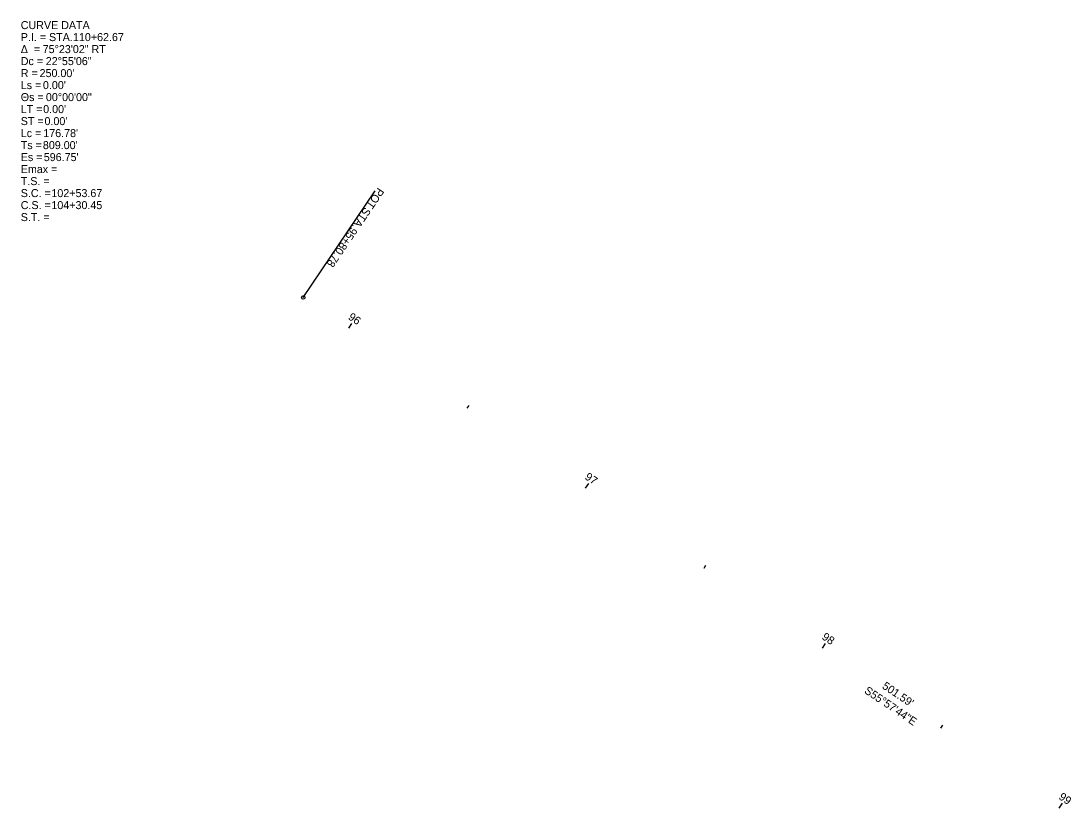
# Model space of a CAD drawing. Extents: x 1600023 to 1602131, y 285824 to 287284.
# Drawn here: x 1600258.1 to 1600625.5, y 287008.6 to 287284.1 of the extents above; entities that cross this region are included whole.
import ezdxf

# ---------------------------------------------------------------- set-up
doc = ezdxf.new("R2010")
doc.units = 0
for name, color, linetype in [('_CIVIL_CONSTRUCTION', 7, 'Continuous'), ('GE_P_Alignment', 7, 'Continuous'), ('PF_P_Grade_Line', 7, 'Continuous'), ('PF_X_Ground_Line', 7, 'Continuous'), ('SC_Scratch6', 7, 'Continuous')]:
    doc.layers.add(name, color=color, linetype=linetype)

msp = doc.modelspace()

# ---------------------------------------------------------------- linework, layer by layer
at = {"layer": '_CIVIL_CONSTRUCTION'}
msp.add_line((1600356.88, 287187.32), (1600382.06, 287224.61), dxfattribs=at)
msp.add_circle((1600356.88, 287187.32), 0.6, dxfattribs=at)
at = {"layer": 'SC_Scratch6'}
for p, q in [((1600372.8, 287176.56), (1600373.92, 287178.22)), ((1600414.24, 287148.57), (1600414.91, 287149.57)), ((1600455.67, 287120.59), (1600456.79, 287122.24)), ((1600497.1, 287092.6), (1600497.78, 287093.59)), ((1600538.54, 287064.61), (1600539.66, 287066.27)), ((1600579.97, 287036.63), (1600580.64, 287037.62)), ((1600621.4, 287008.64), (1600622.52, 287010.3))]:
    msp.add_line(p, q, dxfattribs=at)

# ---------------------------------------------------------------- texts
at = {"layer": '_CIVIL_CONSTRUCTION'}
for s, p in [('POT', (1600383.03, 287225.97)), (' STA. ', (1600379, 287220)), ('95+80.78', (1600373.71, 287212.17))]:
    msp.add_text(s, height=2.8, rotation=235.9623, dxfattribs=at).set_placement(p)
at = {"layer": 'GE_P_Alignment'}
msp.add_text('S55°57\'44"E', height=2.8, rotation=325.9623, dxfattribs=at).set_placement((1600552.95, 287049.08))
at = {"layer": 'PF_P_Grade_Line'}
msp.add_text("501.59'", height=2.8, rotation=325.9623, dxfattribs=at).set_placement((1600559.19, 287050.71))
at = {"layer": 'PF_X_Ground_Line'}
for s, p in [('CURVE DATA', (1600258.03, 287281.25)), ('P.I. = STA. ', (1600258.03, 287277.05)), ('110+62.67', (1600276.3, 287277.05)), ('Δ  = ', (1600258.03, 287272.85)), ('75°23\'02" RT', (1600265.71, 287272.85)), ('Dc = ', (1600258.03, 287268.65)), ('22°55\'06"', (1600266.77, 287268.65)), ('R = ', (1600258.03, 287264.45)), ("250.00'", (1600264.62, 287264.45)), ('Ls = ', (1600258.03, 287260.25)), ("0.00'", (1600265.79, 287260.25)), ('Θs = ', (1600258.03, 287256.05)), ('00°00\'00"', (1600266.83, 287256.05)), ('LT = ', (1600258.03, 287251.85)), ("0.00'", (1600265.88, 287251.85)), ('ST = ', (1600258.03, 287247.65)), ("0.00'", (1600266.34, 287247.65)), ('Lc = ', (1600258.03, 287243.45)), ("176.78'", (1600265.91, 287243.45)), ('Ts = ', (1600258.03, 287239.25)), ("809.00'", (1600265.77, 287239.25)), ('Es = ', (1600258.03, 287235.05)), ("596.75'", (1600266.09, 287235.05)), ('Emax = ', (1600258.03, 287230.85)), ('T.S. = ', (1600258.03, 287226.65)), ('S.C. = ', (1600258.03, 287222.45)), ('102+53.67', (1600268.75, 287222.45)), ('C.S. = ', (1600258.03, 287218.25)), ('104+30.45', (1600268.75, 287218.25)), ('S.T. = ', (1600258.03, 287214.05))]:
    msp.add_text(s, height=2.8, dxfattribs=at).set_placement(p)
at = {"layer": 'SC_Scratch6'}
for s, p in [('96', (1600372.35, 287179.89)), ('97', (1600455.16, 287123.94)), ('98', (1600538.1, 287067.93)), ('99', (1600620.98, 287011.94))]:
    msp.add_text(s, height=2.8, rotation=325.9623, dxfattribs=at).set_placement(p)

doc.saveas('drawing.dxf')
